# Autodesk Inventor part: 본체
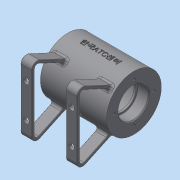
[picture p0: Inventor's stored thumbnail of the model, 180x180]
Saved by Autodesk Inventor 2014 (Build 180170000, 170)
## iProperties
Created: 2021-12
Part Number: 본체
Material: 일반
Document SubType Name: Modeling
Designer: dg
Density: 1 g/cm^3
Appearance: 기본값
Mass: 114.951 g
Surface Area: 354.854 cm^2
Volume: 114.951 cm^3
Author: dg
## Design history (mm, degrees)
sketch "스케치1"
  geometry: L1 (-35, 0)-(35, 0); L2 (-35, 16)-(-23, 16); L3 (-23, 16)-(-23, 14); L4 (-23, 14)-(-21, 14); L5 (-21, 14)-(-21, 21); L6 (-21, 21)-(21, 21); L7 (21, 21)-(21, 14); L8 (21, 14)-(23, 14); L9 (23, 14)-(23, 16); L10 (23, 16)-(35, 16); L11 (35, 16)-(35, 29); L12 (35, 29)-(-35, 29); L13 (-35, 29)-(-35, 16); 2 further points
  constraints: 26 end point, 9 parallel, 3 collinear, 2 horizontal alignment, 2 perpendicular, 2 vertical alignment, 1 coincident, 1 horizontal, 1 midpoint
  dimensions: "d0" = 70 distance of L1.start L1.end; "d1" = 32 diameter of L2 L1; "d2" = 28 diameter of L4 L1; "d3" = 42 diameter of L6 L1; "d4" = 58 diameter of L12 L1; "d5" = 12 distance of L2.start L2.end; "d7" = 42 distance of L5.end L6.end
revolve "회전1" sketch "스케치1" stored, may be unused: angle "d8" = 90 deg
node "작업 평면1"
sketch "스케치2"
  geometry: L1 (-22.743, -17.993)-(-40, -55); L2 (-40, -55)-(40, -55); L3 (40, -55)-(22.743, -17.993); L4 (-20.574, -20.438)-(-35.291, -52); L5 (-35.291, -52)-(35.291, -52); L6 (35.291, -52)-(20.574, -20.438); A1 r 29 centre (0, 0) between (-22.743, -17.993) and (22.743, -17.993) reference; 1 further point
  constraints: 12 end point, 4 point on circle, 3 parallel, 2 horizontal alignment, 1 horizontal
  dimensions: "d10" = 80 distance of L2.end L1.end; "d11" = 3 distance between parallel lines of L4 L1; "d12" = 3 distance between parallel lines of L3 L6; "d13" = 3 distance between parallel lines of L2 L5; "d14" = 55 distance from line of L2 point (0, 0); "d15" = 65 deg angle of L2 L3
extrude "돌출1" join sketch "스케치2" distance "d16" = 12; taper "d17" = 0 deg
node "작업 평면2"
fillet "모깎기1" dims "d18" = 6, "d19" = 3
sketch "스케치3"
  geometry: C1 r 29 at (0, 0) reference; 1 further point
  constraints: 1 vertical alignment
  dimensions: "d20" = 21 distance of C1.centre point (0, 21)
hole "구멍1" sketch "스케치3" at (0, 21) diameter "d21" = 3.242; stored, may be unused: countersink angle "d25" = 90 deg, drill point angle "d27" = 118 deg; dims "d22" = 8, "d23" = 4, "d24" = 2, "d26" = 10
sketch "스케치4"
  geometry: L1 (0, 0)-(10.945, -30.07); L2 (0, 0)-(0, -48.02); L3 (10.945, -30.07)-(16.583, -28.018); L4 (16.583, -28.018)-(14.601, -22.573); L5 (14.601, -22.573)-(8.963, -24.625)
  constraints: 10 end point, 3 perpendicular, 1 point on line, 1 vertical
  dimensions: "d31" = 32 distance of L1.start L1.end; "d32" = 20 deg angle of L1 L2; "d33" = 12 diameter of L4 L1; "d34" = 5.79433 distance between parallel lines of L3 L5
revolve "회전2" sketch "스케치4" stored, may be unused: angle "d35" = 90 deg
hole "구멍2" diameter "d38" = 4.917; stored, may be unused: countersink angle "d42" = 90 deg, drill point angle "d44" = 118 deg; dims "d36" = 10, "d37" = 10, "d39" = 8, "d40" = 4, "d41" = 2, "d43" = 10
node "작업 평면3"
sketch "스케치5"
  geometry: C1 r 5 at (0, 0); C2 r 1.5 at (0, 0); 1 further point
  constraints: 2 centre point, 2 coincident
  dimensions: "d46" = 10 diameter of C1; "d47" = 3 diameter of C2
extrude "돌출2" join sketch "스케치5" stored distance "d48" = 12; taper "d49" = 0 deg
extrude "돌출3" cut sketch "스케치5" stored distance "d50" = 12; taper "d51" = 0 deg
hole "구멍3" diameter "d54" = 4.917; stored, may be unused: countersink angle "d58" = 90 deg, drill point angle "d60" = 118 deg; dims "d52" = 10, "d53" = 10, "d55" = 6, "d56" = 4, "d57" = 2, "d59" = 8
sketch "스케치6"
  geometry: L1 (0, 61.164)-(0, 0) reference; C1 r 3 at (6, 48.582); C2 r 3 at (6, 12.582); C3 r 3 at (54, 48.582); C4 r 3 at (54, 12.582); 1 further point
  constraints: 4 centre point, 3 equal radius, 2 horizontal alignment, 2 vertical alignment
  dimensions: "d61" = 36 distance of C2.centre C1.centre; "d62" = 6 distance from line of C1.centre L1; "d63" = 48 distance of C3.centre C1.centre; "d64" = 6 diameter of C1; "d65" = 18 vertical distance of point (30, 30.582) C1.centre
extrude "돌출4" cut sketch "스케치6" stored distance "d66" = 12; taper "d67" = 0 deg
fillet "모깎기2" dims "d68" = 0.5
fillet "모깎기3" dims "d69" = 3, "d70" = 1
chamfer "모따기1" distance "d71" = 1; stored, may be unused: second distance "d72" = 2, angle "d73" = 45 deg
fillet "모깎기4" dims "d74" = 0.3, "d75" = 3
node "작업 평면4"
sketch "스케치7"
  geometry: L1 (-35, -29)-(-35, 29) reference; 2 further points
  constraints: 2 coincident, 1 other
  dimensions: "d80" = 35 distance from line of point (0, 0) L1 (derived); "d81" = 29 vertical distance of point (0, 0) L1.end (derived)
feature "엠보싱1" sketch "스케치7" dims "d0" = 70, "d1" = 32, "d2" = 28, "d3" = 42, "d4" = 58, "d5" = 12, "d7" = 42, "d78" = 0.5, "d79" = 0
node "솔리드1"
mirror "대칭1"
pattern_circular "원형 패턴1" dims angle "d29" = 360 deg
mirror "대칭2"
other parameters: "d9" = -5, "d45" = 32
